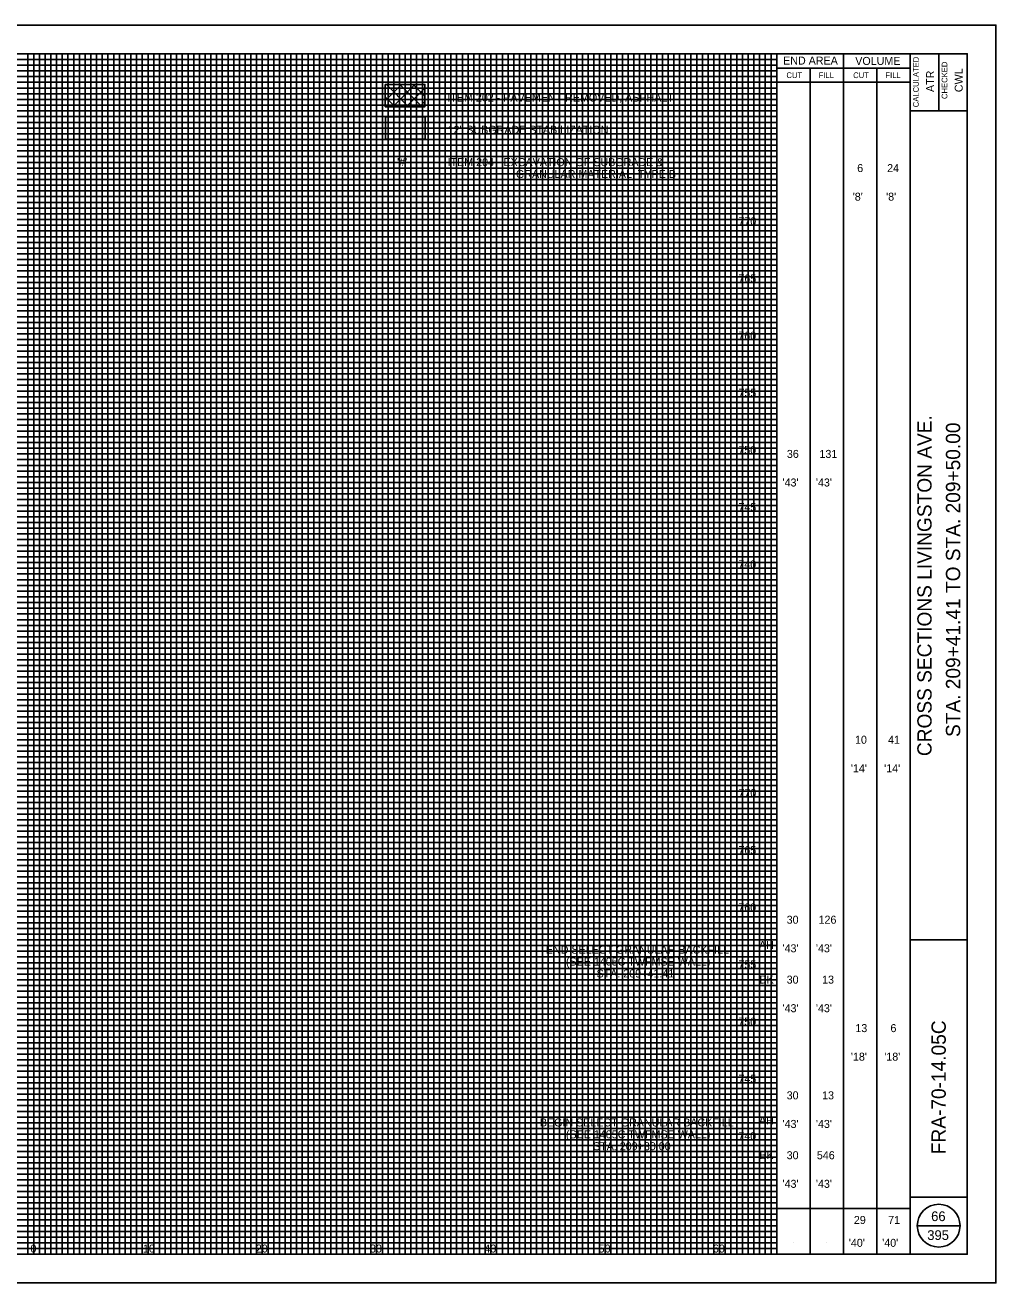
# Model space of a CAD drawing. Extents: x -10 to 160, y -2 to 568.
# Drawn here: x 75.1 to 160, y 342.5 to 452.5 of the extents above; entities that cross this region are included whole.
import ezdxf

# ---------------------------------------------------------------- set-up
doc = ezdxf.new("R2010")
doc.units = 0
for name, color, linetype in [('DR_P_Text', 7, 'Continuous'), ('SH_Border', 7, 'Continuous'), ('SH_Cut_Line', 7, 'Continuous'), ('SH_Data', 7, 'Continuous'), ('SH_Major_Grid_Line', 7, 'Continuous'), ('SH_Minor_Grid_Line', 7, 'Continuous'), ('XS_P_Annotation', 7, 'Continuous'), ('XS_P_Undercut', 7, 'Continuous'), ('XS_X_Pavt', 7, 'Continuous')]:
    doc.layers.add(name, color=color, linetype=linetype)

msp = doc.modelspace()

# ---------------------------------------------------------------- linework, layer by layer
at = {"layer": 'SH_Border'}
for p, q in [((152.5, 345), (152.5, 450)), ((155, 450), (155, 445)), ((152.5, 445), (157.5, 445)), ((152.5, 372.5), (157.5, 372.5)), ((152.5, 350), (157.5, 350))]:
    msp.add_line(p, q, dxfattribs=at)
msp.add_lwpolyline([(0, 450), (157.5, 450), (157.5, 345), (0, 345)], close=True, dxfattribs=at)
at = {"layer": 'SH_Cut_Line'}
msp.add_lwpolyline([(-10, 342.5), (160, 342.5), (160, 452.5), (-10, 452.5)], close=True, dxfattribs=at)
at = {"layer": 'SH_Data'}
for p, q in [((140.83, 345), (140.83, 450)), ((146.67, 345), (146.67, 450)), ((140.83, 448.75), (152.5, 448.75)), ((143.75, 345), (143.75, 448.75)), ((149.58, 345), (149.58, 448.75)), ((140.83, 447.5), (152.5, 447.5)), ((140.83, 349), (152.5, 349)), ((153.12, 347.5), (156.88, 347.5)), ((142.29, 346), (142.29, 346)), ((145.21, 346), (145.21, 346)), ((148.12, 346), (148.12, 346)), ((151.04, 346), (151.04, 346))]:
    msp.add_line(p, q, dxfattribs=at)
msp.add_circle((155, 347.5), 1.87, dxfattribs=at)
at = {"layer": 'SH_Major_Grid_Line'}
for p, q in [((75.83, 345), (75.83, 450)), ((80.83, 345), (80.83, 450)), ((85.83, 345), (85.83, 450)), ((90.83, 345), (90.83, 450)), ((95.83, 345), (95.83, 450)), ((100.83, 345), (100.83, 450)), ((105.83, 345), (105.83, 450)), ((110.83, 345), (110.83, 450)), ((115.83, 345), (115.83, 450)), ((120.83, 345), (120.83, 450)), ((125.83, 345), (125.83, 450)), ((130.83, 345), (130.83, 450)), ((135.83, 345), (135.83, 450)), ((5.83, 445), (140.83, 445)), ((5.83, 440), (140.83, 440)), ((5.83, 435), (140.83, 435)), ((5.83, 430), (140.83, 430)), ((5.83, 425), (140.83, 425)), ((5.83, 420), (140.83, 420)), ((5.83, 415), (140.83, 415)), ((5.83, 410), (140.83, 410)), ((5.83, 405), (140.83, 405)), ((5.83, 400), (140.83, 400)), ((5.83, 395), (140.83, 395)), ((5.83, 390), (140.83, 390)), ((5.83, 385), (140.83, 385)), ((5.83, 380), (140.83, 380)), ((5.83, 375), (140.83, 375)), ((5.83, 370), (140.83, 370)), ((5.83, 365), (140.83, 365)), ((5.83, 360), (140.83, 360)), ((5.83, 355), (140.83, 355)), ((5.83, 350), (140.83, 350))]:
    msp.add_line(p, q, dxfattribs=at)
at = {"layer": 'SH_Minor_Grid_Line'}
for p, q in [((75.33, 345), (75.33, 450)), ((76.33, 345), (76.33, 450)), ((76.83, 345), (76.83, 450)), ((77.33, 345), (77.33, 450)), ((77.83, 345), (77.83, 450)), ((78.33, 345), (78.33, 450)), ((78.83, 345), (78.83, 450)), ((79.33, 345), (79.33, 450)), ((79.83, 345), (79.83, 450)), ((80.33, 345), (80.33, 450)), ((81.33, 345), (81.33, 450)), ((81.83, 345), (81.83, 450)), ((82.33, 345), (82.33, 450)), ((82.83, 345), (82.83, 450)), ((83.33, 345), (83.33, 450)), ((83.83, 345), (83.83, 450)), ((84.33, 345), (84.33, 450)), ((84.83, 345), (84.83, 450)), ((85.33, 345), (85.33, 450)), ((86.33, 345), (86.33, 450)), ((86.83, 345), (86.83, 450)), ((87.33, 345), (87.33, 450)), ((87.83, 345), (87.83, 450)), ((88.33, 345), (88.33, 450)), ((88.83, 345), (88.83, 450)), ((89.33, 345), (89.33, 450)), ((89.83, 345), (89.83, 450)), ((90.33, 345), (90.33, 450)), ((91.33, 345), (91.33, 450)), ((91.83, 345), (91.83, 450)), ((92.33, 345), (92.33, 450)), ((92.83, 345), (92.83, 450)), ((93.33, 345), (93.33, 450)), ((93.83, 345), (93.83, 450)), ((94.33, 345), (94.33, 450)), ((94.83, 345), (94.83, 450)), ((95.33, 345), (95.33, 450)), ((96.33, 345), (96.33, 450)), ((96.83, 345), (96.83, 450)), ((97.33, 345), (97.33, 450)), ((97.83, 345), (97.83, 450)), ((98.33, 345), (98.33, 450)), ((98.83, 345), (98.83, 450)), ((99.33, 345), (99.33, 450)), ((99.83, 345), (99.83, 450)), ((100.33, 345), (100.33, 450)), ((101.33, 345), (101.33, 450)), ((101.83, 345), (101.83, 450)), ((102.33, 345), (102.33, 450)), ((102.83, 345), (102.83, 450)), ((103.33, 345), (103.33, 450)), ((103.83, 345), (103.83, 450)), ((104.33, 345), (104.33, 450)), ((104.83, 345), (104.83, 450)), ((105.33, 345), (105.33, 450)), ((106.33, 345), (106.33, 450)), ((106.83, 345), (106.83, 450)), ((107.33, 345), (107.33, 450)), ((107.83, 345), (107.83, 450)), ((108.33, 345), (108.33, 450)), ((108.83, 345), (108.83, 450)), ((109.33, 345), (109.33, 450)), ((109.83, 345), (109.83, 450)), ((110.33, 345), (110.33, 450)), ((111.33, 345), (111.33, 450)), ((111.83, 345), (111.83, 450)), ((112.33, 345), (112.33, 450)), ((112.83, 345), (112.83, 450)), ((113.33, 345), (113.33, 450)), ((113.83, 345), (113.83, 450)), ((114.33, 345), (114.33, 450)), ((114.83, 345), (114.83, 450)), ((115.33, 345), (115.33, 450)), ((116.33, 345), (116.33, 450)), ((116.83, 345), (116.83, 450)), ((117.33, 345), (117.33, 450)), ((117.83, 345), (117.83, 450)), ((118.33, 345), (118.33, 450)), ((118.83, 345), (118.83, 450)), ((119.33, 345), (119.33, 450)), ((119.83, 345), (119.83, 450)), ((120.33, 345), (120.33, 450)), ((121.33, 345), (121.33, 450)), ((121.83, 345), (121.83, 450)), ((122.33, 345), (122.33, 450)), ((122.83, 345), (122.83, 450)), ((123.33, 345), (123.33, 450)), ((123.83, 345), (123.83, 450)), ((124.33, 345), (124.33, 450)), ((124.83, 345), (124.83, 450)), ((125.33, 345), (125.33, 450)), ((126.33, 345), (126.33, 450)), ((126.83, 345), (126.83, 450)), ((127.33, 345), (127.33, 450)), ((127.83, 345), (127.83, 450)), ((128.33, 345), (128.33, 450)), ((128.83, 345), (128.83, 450)), ((129.33, 345), (129.33, 450)), ((129.83, 345), (129.83, 450)), ((130.33, 345), (130.33, 450)), ((131.33, 345), (131.33, 450)), ((131.83, 345), (131.83, 450)), ((132.33, 345), (132.33, 450)), ((132.83, 345), (132.83, 450)), ((133.33, 345), (133.33, 450)), ((133.83, 345), (133.83, 450)), ((134.33, 345), (134.33, 450)), ((134.83, 345), (134.83, 450)), ((135.33, 345), (135.33, 450)), ((136.33, 345), (136.33, 450)), ((136.83, 345), (136.83, 450)), ((137.33, 345), (137.33, 450)), ((137.83, 345), (137.83, 450)), ((138.33, 345), (138.33, 450)), ((138.83, 345), (138.83, 450)), ((139.33, 345), (139.33, 450)), ((139.83, 345), (139.83, 450)), ((140.33, 345), (140.33, 450)), ((5.83, 449.5), (140.83, 449.5)), ((5.83, 449), (140.83, 449)), ((5.83, 448.5), (140.83, 448.5)), ((5.83, 448), (140.83, 448)), ((5.83, 447.5), (140.83, 447.5)), ((5.83, 447), (140.83, 447)), ((5.83, 446.5), (140.83, 446.5)), ((5.83, 446), (140.83, 446)), ((5.83, 445.5), (140.83, 445.5)), ((5.83, 444.5), (140.83, 444.5)), ((5.83, 444), (140.83, 444)), ((5.83, 443.5), (140.83, 443.5)), ((5.83, 443), (140.83, 443)), ((5.83, 442.5), (140.83, 442.5)), ((5.83, 442), (140.83, 442)), ((5.83, 441.5), (140.83, 441.5)), ((5.83, 441), (140.83, 441)), ((5.83, 440.5), (140.83, 440.5)), ((5.83, 439.5), (140.83, 439.5)), ((5.83, 439), (140.83, 439)), ((5.83, 438.5), (140.83, 438.5)), ((5.83, 438), (140.83, 438)), ((5.83, 437.5), (140.83, 437.5)), ((5.83, 437), (140.83, 437)), ((5.83, 436.5), (140.83, 436.5)), ((5.83, 436), (140.83, 436)), ((5.83, 435.5), (140.83, 435.5)), ((5.83, 434.5), (140.83, 434.5)), ((5.83, 434), (140.83, 434)), ((5.83, 433.5), (140.83, 433.5)), ((5.83, 433), (140.83, 433)), ((5.83, 432.5), (140.83, 432.5)), ((5.83, 432), (140.83, 432)), ((5.83, 431.5), (140.83, 431.5)), ((5.83, 431), (140.83, 431)), ((5.83, 430.5), (140.83, 430.5)), ((5.83, 429.5), (140.83, 429.5)), ((5.83, 429), (140.83, 429)), ((5.83, 428.5), (140.83, 428.5)), ((5.83, 428), (140.83, 428)), ((5.83, 427.5), (140.83, 427.5)), ((5.83, 427), (140.83, 427)), ((5.83, 426.5), (140.83, 426.5)), ((5.83, 426), (140.83, 426)), ((5.83, 425.5), (140.83, 425.5)), ((5.83, 424.5), (140.83, 424.5)), ((5.83, 424), (140.83, 424)), ((5.83, 423.5), (140.83, 423.5)), ((5.83, 423), (140.83, 423)), ((5.83, 422.5), (140.83, 422.5)), ((5.83, 422), (140.83, 422)), ((5.83, 421.5), (140.83, 421.5)), ((5.83, 421), (140.83, 421)), ((5.83, 420.5), (140.83, 420.5)), ((5.83, 419.5), (140.83, 419.5)), ((5.83, 419), (140.83, 419)), ((5.83, 418.5), (140.83, 418.5)), ((5.83, 418), (140.83, 418)), ((5.83, 417.5), (140.83, 417.5)), ((5.83, 417), (140.83, 417)), ((5.83, 416.5), (140.83, 416.5)), ((5.83, 416), (140.83, 416)), ((5.83, 415.5), (140.83, 415.5)), ((5.83, 414.5), (140.83, 414.5)), ((5.83, 414), (140.83, 414)), ((5.83, 413.5), (140.83, 413.5)), ((5.83, 413), (140.83, 413)), ((5.83, 412.5), (140.83, 412.5)), ((5.83, 412), (140.83, 412)), ((5.83, 411.5), (140.83, 411.5)), ((5.83, 411), (140.83, 411)), ((5.83, 410.5), (140.83, 410.5)), ((5.83, 409.5), (140.83, 409.5)), ((5.83, 409), (140.83, 409)), ((5.83, 408.5), (140.83, 408.5)), ((5.83, 408), (140.83, 408)), ((5.83, 407.5), (140.83, 407.5)), ((5.83, 407), (140.83, 407)), ((5.83, 406.5), (140.83, 406.5)), ((5.83, 406), (140.83, 406)), ((5.83, 405.5), (140.83, 405.5)), ((5.83, 404.5), (140.83, 404.5)), ((5.83, 404), (140.83, 404)), ((5.83, 403.5), (140.83, 403.5)), ((5.83, 403), (140.83, 403)), ((5.83, 402.5), (140.83, 402.5)), ((5.83, 402), (140.83, 402)), ((5.83, 401.5), (140.83, 401.5)), ((5.83, 401), (140.83, 401)), ((5.83, 400.5), (140.83, 400.5)), ((5.83, 399.5), (140.83, 399.5)), ((5.83, 399), (140.83, 399)), ((5.83, 398.5), (140.83, 398.5)), ((5.83, 398), (140.83, 398)), ((5.83, 397.5), (140.83, 397.5)), ((5.83, 397), (140.83, 397)), ((5.83, 396.5), (140.83, 396.5)), ((5.83, 396), (140.83, 396)), ((5.83, 395.5), (140.83, 395.5)), ((5.83, 394.5), (140.83, 394.5)), ((5.83, 394), (140.83, 394)), ((5.83, 393.5), (140.83, 393.5)), ((5.83, 393), (140.83, 393)), ((5.83, 392.5), (140.83, 392.5)), ((5.83, 392), (140.83, 392)), ((5.83, 391.5), (140.83, 391.5)), ((5.83, 391), (140.83, 391)), ((5.83, 390.5), (140.83, 390.5)), ((5.83, 389.5), (140.83, 389.5)), ((5.83, 389), (140.83, 389)), ((5.83, 388.5), (140.83, 388.5)), ((5.83, 388), (140.83, 388)), ((5.83, 387.5), (140.83, 387.5)), ((5.83, 387), (140.83, 387)), ((5.83, 386.5), (140.83, 386.5)), ((5.83, 386), (140.83, 386)), ((5.83, 385.5), (140.83, 385.5)), ((5.83, 384.5), (140.83, 384.5)), ((5.83, 384), (140.83, 384)), ((5.83, 383.5), (140.83, 383.5)), ((5.83, 383), (140.83, 383)), ((5.83, 382.5), (140.83, 382.5)), ((5.83, 382), (140.83, 382)), ((5.83, 381.5), (140.83, 381.5)), ((5.83, 381), (140.83, 381)), ((5.83, 380.5), (140.83, 380.5)), ((5.83, 379.5), (140.83, 379.5)), ((5.83, 379), (140.83, 379)), ((5.83, 378.5), (140.83, 378.5)), ((5.83, 378), (140.83, 378)), ((5.83, 377.5), (140.83, 377.5)), ((5.83, 377), (140.83, 377)), ((5.83, 376.5), (140.83, 376.5)), ((5.83, 376), (140.83, 376)), ((5.83, 375.5), (140.83, 375.5)), ((5.83, 374.5), (140.83, 374.5)), ((5.83, 374), (140.83, 374)), ((5.83, 373.5), (140.83, 373.5)), ((5.83, 373), (140.83, 373)), ((5.83, 372.5), (140.83, 372.5)), ((5.83, 372), (140.83, 372)), ((5.83, 371.5), (140.83, 371.5)), ((5.83, 371), (140.83, 371)), ((5.83, 370.5), (140.83, 370.5)), ((5.83, 369.5), (140.83, 369.5)), ((5.83, 369), (140.83, 369)), ((5.83, 368.5), (140.83, 368.5)), ((5.83, 368), (140.83, 368)), ((5.83, 367.5), (140.83, 367.5)), ((5.83, 367), (140.83, 367)), ((5.83, 366.5), (140.83, 366.5)), ((5.83, 366), (140.83, 366)), ((5.83, 365.5), (140.83, 365.5)), ((5.83, 364.5), (140.83, 364.5)), ((5.83, 364), (140.83, 364)), ((5.83, 363.5), (140.83, 363.5)), ((5.83, 363), (140.83, 363)), ((5.83, 362.5), (140.83, 362.5)), ((5.83, 362), (140.83, 362)), ((5.83, 361.5), (140.83, 361.5)), ((5.83, 361), (140.83, 361)), ((5.83, 360.5), (140.83, 360.5)), ((5.83, 359.5), (140.83, 359.5)), ((5.83, 359), (140.83, 359)), ((5.83, 358.5), (140.83, 358.5)), ((5.83, 358), (140.83, 358)), ((5.83, 357.5), (140.83, 357.5)), ((5.83, 357), (140.83, 357)), ((5.83, 356.5), (140.83, 356.5)), ((5.83, 356), (140.83, 356)), ((5.83, 355.5), (140.83, 355.5)), ((5.83, 354.5), (140.83, 354.5)), ((5.83, 354), (140.83, 354)), ((5.83, 353.5), (140.83, 353.5)), ((5.83, 353), (140.83, 353)), ((5.83, 352.5), (140.83, 352.5)), ((5.83, 352), (140.83, 352)), ((5.83, 351.5), (140.83, 351.5)), ((5.83, 351), (140.83, 351)), ((5.83, 350.5), (140.83, 350.5)), ((5.83, 349.5), (140.83, 349.5)), ((5.83, 349), (140.83, 349)), ((5.83, 348.5), (140.83, 348.5)), ((5.83, 348), (140.83, 348)), ((5.83, 347.5), (140.83, 347.5)), ((5.83, 347), (140.83, 347)), ((5.83, 346.5), (140.83, 346.5)), ((5.83, 346), (140.83, 346)), ((5.83, 345.5), (140.83, 345.5))]:
    msp.add_line(p, q, dxfattribs=at)
at = {"layer": 'XS_P_Annotation'}
for points in [[(106.59, 447.31), (110.05, 447.31), (110.05, 445.36), (106.59, 445.36)], [(106.61, 444.48), (110.08, 444.48), (110.08, 442.54), (106.61, 442.54)]]:
    msp.add_lwpolyline(points, close=True, dxfattribs=at)
at = {"layer": 'XS_P_Undercut'}
msp.add_lwpolyline([(106.61, 442.54), (110.08, 442.54), (110.08, 444.48), (106.61, 444.48), (106.61, 442.54)], dxfattribs=at)
at = {"layer": 'XS_X_Pavt'}
for p, q in [((106.59, 445.89), (108, 447.31)), ((106.68, 447.31), (108.62, 445.36)), ((107.24, 445.36), (109.18, 447.31)), ((107.85, 447.31), (109.8, 445.36)), ((108.42, 445.36), (110.05, 447)), ((109.03, 447.31), (110.05, 446.29)), ((106.59, 446.22), (107.44, 445.36)), ((109.59, 445.36), (110.05, 445.82))]:
    msp.add_line(p, q, dxfattribs=at)

# ---------------------------------------------------------------- texts
at = {"layer": 'DR_P_Text'}
for s, p in [("'#'", (107.62, 440.17)), ('6', (147.87, 439.65)), ('24', (150.49, 439.65)), ("'8'", (147.48, 437.15)), ("'8'", (150.4, 437.15)), ('770', (137.48, 435)), ('765', (137.48, 430)), ('760', (137.47, 425)), ('755', (137.48, 420)), ('750', (137.47, 415)), ('36', (141.72, 414.65)), ('131', (144.57, 414.65)), ("'43'", (141.34, 412.15)), ("'43'", (144.26, 412.15)), ('745', (137.48, 410)), ('740', (137.47, 405)), ('10', (147.68, 389.65)), ('41', (150.57, 389.65)), ("'14'", (147.32, 387.15)), ("'14'", (150.23, 387.15)), ('770', (137.48, 385)), ('765', (137.48, 380)), ('760', (137.47, 375)), ('30', (141.7, 373.91)), ('126', (144.49, 373.91)), ('AH', (139.28, 371.71)), ("'43'", (141.34, 371.41)), ("'43'", (144.26, 371.41)), ('755', (137.48, 370)), ('BK', (139.32, 368.68)), ('30', (141.7, 368.67)), ('13', (144.8, 368.67)), ("'43'", (141.34, 366.17)), ("'43'", (144.26, 366.17)), ('750', (137.47, 365)), ('13', (147.71, 364.43)), ('6', (150.78, 364.43)), ("'18'", (147.32, 361.93)), ("'18'", (150.24, 361.93)), ('745', (137.48, 360)), ('30', (141.7, 358.55)), ('13', (144.8, 358.55)), ('AH', (139.28, 356.35)), ("'43'", (141.34, 356.05)), ("'43'", (144.26, 356.05)), ('740', (137.47, 355)), ('BK', (139.32, 353.32)), ('30', (141.7, 353.31)), ('546', (144.34, 353.31)), ("'43'", (141.34, 350.81)), ("'43'", (144.26, 350.81)), ('29', (147.58, 347.65)), ('71', (150.58, 347.65)), ('0', (75.55, 345.15)), ('0', (75.55, 345.15)), ('10', (85.39, 345.15)), ('20', (95.26, 345.15)), ('30', (105.25, 345.15)), ('40', (115.25, 345.15)), ('50', (125.25, 345.15)), ('60', (135.25, 345.15)), ("'40'", (147.14, 345.65)), ("'40'", (150.06, 345.65))]:
    msp.add_text(s, height=0.7, dxfattribs=at).set_placement(p)
at = {"layer": 'SH_Data'}
for s, height, p in [('END AREA', 0.7, (141.39, 449.05)), ('VOLUME', 0.7, (147.7, 449.02)), ('CUT', 0.5, (141.68, 447.87)), ('FILL', 0.5, (144.5, 447.87)), ('CUT', 0.5, (147.52, 447.87)), ('FILL', 0.5, (150.34, 447.87)), ('66', 0.85, (154.34, 347.9)), ('395', 0.85, (154, 346.25))]:
    msp.add_text(s, height=height, dxfattribs=at).set_placement(p)
for s, height, p in [('CALCULATED', 0.5, (153.26, 445.32)), ('CHECKED', 0.5, (155.76, 446.04)), ('ATR', 0.7, (154.6, 446.65)), ('CWL', 0.7, (157.1, 446.64)), ('CROSS SECTIONS LIVINGSTON AVE.', 1.25, (154.38, 388.57)), ('STA. 209+41.41 TO STA. 209+50.00', 1.25, (156.88, 390.24)), ('FRA-70-14.05C', 1.25, (155.62, 353.75))]:
    msp.add_text(s, height=height, rotation=90, dxfattribs=at).set_placement(p)
at = {"layer": 'XS_P_Annotation'}
for s, p in [('ITEM 202 - PAVEMENT REMOVED, ASPHALT', (112.02, 445.82)), ('12" SUBGRADE STABILIZATION', (112.04, 443)), ('ITEM 204 - EXCAVATION OF SUBGRADE &', (112.04, 440.17)), ('GRANULAR MATERIAL, TYPE B', (118.02, 439.13)), ('END SELECT GRANULAR BACKFILL', (120.63, 371.29)), ('(SEE 1405C TWFMSE WALL)', (122.39, 370.25)), ('STA. 209+41.41', (125.07, 369.21)), ('BEGIN SELECT GRANULAR BACKFILL', (120.11, 356.18)), ('(SEE 1405C TWFMSE WALL)', (122.39, 355.14)), ('STA. 209+30.00', (124.76, 354.1))]:
    msp.add_text(s, height=0.7, dxfattribs=at).set_placement(p)

doc.saveas('drawing.dxf')
